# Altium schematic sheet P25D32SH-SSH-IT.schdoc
size 127 x 101 mm
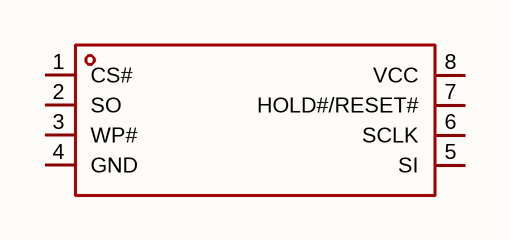
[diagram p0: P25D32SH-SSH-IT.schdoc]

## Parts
U?  p25d32sh-ssh-it  [SOP-8_L4.9-W3.9-P1.27-LS6.0-BL]  (value not drawn)

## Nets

Not connected (* = marked no-connect by the designer): U? 1(CS#) 2(SO) 3(WP#) 4(GND) 5(SI) 6(SCLK) 7(HOLD#/RESET#) 8(VCC)

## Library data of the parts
U? = p25d32sh-ssh-it: 接口类型:SPI;存储容量:32Mbit;时钟频率(fc):120MHz;; Manufacturer: PUYA(普冉); AddInBom: yes; ModelId: 75c24a7891ee4dd6bdac16a7163ff87e; ModelName: SOP-8_L4.9-W3.9-P1.27-LS6.0-BL-1; ModelTransform: 192.913,236.22,0,0,0,0,-0.393,2.749,0; Interface: SPI; Memory Size: 32Mbit; Clock Frequency: 120MHz; Voltage - Supply: 2.3V~3.6V; Standby Supply Current: 10uA; Program / Erase Cycles: 100000次; Write Cycle Time (tWC): 12ms; Page Programming Time (Tpp): 1.6ms; Block Erase Time(tBE): 30ms@(32KB); Data Retention - TDR (Year): 20年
